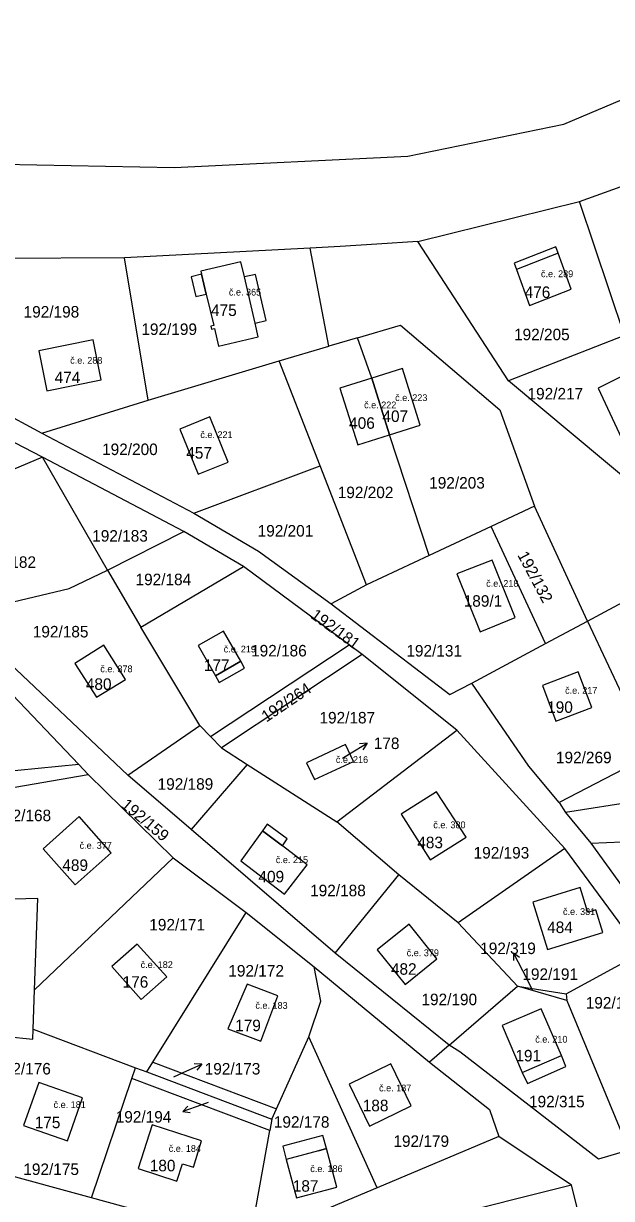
# Model space of a CAD drawing. Extents: x -887272 to -877616, y -1026687 to -1019819.
# Drawn here: x -882288.7 to -882201.9, y -1024193.7 to -1024020.3 of the extents above; entities that cross this region are included whole.
import ezdxf

# ---------------------------------------------------------------- set-up
doc = ezdxf.new("R2010")
doc.units = 0
for name, color, linetype in [('Definiční body', 7, 'Continuous'), ('Hranice parcel', 7, 'Continuous'), ('Parcelní čísla', 7, 'Continuous'), ('Polygon budovy', 7, 'Continuous'), ('Pop  PČ popisy', 7, 'Continuous'), ('Vnitřní kresba', 7, 'Continuous')]:
    doc.layers.add(name, color=color, linetype=linetype)

msp = doc.modelspace()

# ---------------------------------------------------------------- linework, layer by layer
at = {"layer": 'Hranice parcel'}
for p, q in [((-882206.58, -1024046.52), (-882188.26, -1024039.89)), ((-882230.46, -1024052.45), (-882206.58, -1024046.52)), ((-882199.93, -1024066.33), (-882206.58, -1024046.52)), ((-882217.07, -1024073.03), (-882230.46, -1024052.45)), ((-882246.33, -1024053.44), (-882273.78, -1024054.86)), ((-882243.61, -1024067.89), (-882246.33, -1024053.44)), ((-882273.78, -1024054.86), (-882294.43, -1024054.96)), ((-882270.28, -1024075.87), (-882273.78, -1024054.86)), ((-882199.93, -1024066.33), (-882217.07, -1024073.03)), ((-882250.94, -1024070.04), (-882243.61, -1024067.89)), ((-882239.34, -1024066.64), (-882243.61, -1024067.89)), ((-882237.27, -1024072.6), (-882239.34, -1024066.64)), ((-882270.28, -1024075.87), (-882250.94, -1024070.04)), ((-882244.88, -1024085.57), (-882250.94, -1024070.04)), ((-882237.27, -1024072.6), (-882234.62, -1024081)), ((-882196.2, -1024090.44), (-882217.07, -1024073.03)), ((-882294.27, -1024076.26), (-882285.96, -1024080.75)), ((-882285.96, -1024080.75), (-882270.28, -1024075.87)), ((-882285.87, -1024084.26), (-882291.31, -1024081.48)), ((-882285.96, -1024080.75), (-882263.54, -1024092.56)), ((-882228.8, -1024098.78), (-882234.62, -1024081)), ((-882285.87, -1024084.26), (-882304.9, -1024092.29)), ((-882276.26, -1024100.98), (-882285.87, -1024084.26)), ((-882265.03, -1024095.27), (-882285.87, -1024084.26)), ((-882263.54, -1024092.56), (-882244.88, -1024085.57)), ((-882238.02, -1024103.14), (-882244.88, -1024085.57)), ((-882213.21, -1024091.51), (-882219.65, -1024094.51)), ((-882205.42, -1024108.48), (-882213.21, -1024091.51)), ((-882276.26, -1024100.98), (-882265.03, -1024095.27)), ((-882256.19, -1024100.43), (-882265.03, -1024095.27)), ((-882219.65, -1024094.51), (-882228.8, -1024098.78)), ((-882211.61, -1024111.8), (-882219.65, -1024094.51)), ((-882228.8, -1024098.78), (-882238.02, -1024103.14)), ((-882276.26, -1024100.98), (-882271.37, -1024109.4)), ((-882271.37, -1024109.4), (-882256.19, -1024100.43)), ((-882240.6, -1024111.96), (-882256.19, -1024100.43)), ((-882238.02, -1024103.14), (-882243.24, -1024105.91)), ((-882205.42, -1024108.48), (-882198.92, -1024105.01)), ((-882273.27, -1024131.24), (-882298.33, -1024107.54)), ((-882262.64, -1024123.91), (-882271.37, -1024109.4)), ((-882211.61, -1024111.8), (-882205.42, -1024108.48)), ((-882261.07, -1024125.53), (-882240.6, -1024111.96)), ((-882238.67, -1024113.39), (-882240.6, -1024111.96)), ((-882222.5, -1024117.62), (-882211.61, -1024111.8)), ((-882238.67, -1024113.39), (-882259.45, -1024127.19)), ((-882224.7, -1024124.59), (-882238.67, -1024113.39)), ((-882273.27, -1024131.24), (-882262.64, -1024123.91)), ((-882262.64, -1024123.91), (-882261.07, -1024125.53)), ((-882242.43, -1024138.12), (-882224.7, -1024124.59)), ((-882224.7, -1024124.59), (-882208.75, -1024142.05)), ((-882259.45, -1024127.19), (-882261.07, -1024125.53)), ((-882259.45, -1024127.19), (-882255.64, -1024129.63)), ((-882280.53, -1024129.66), (-882306.6, -1024132.25)), ((-882280.53, -1024129.66), (-882279.12, -1024131.14)), ((-882255.64, -1024129.63), (-882263.95, -1024139.24)), ((-882255.64, -1024129.63), (-882242.43, -1024138.12)), ((-882295.03, -1024133.84), (-882279.12, -1024131.14)), ((-882279.12, -1024131.14), (-882266.59, -1024143.44)), ((-882263.95, -1024139.24), (-882273.27, -1024131.24)), ((-882190.49, -1024133.91), (-882208.64, -1024136.73)), ((-882209.58, -1024135.28), (-882208.64, -1024136.73)), ((-882208.64, -1024136.73), (-882204.92, -1024141.27)), ((-882242.67, -1024157.52), (-882263.95, -1024139.24)), ((-882233.24, -1024145.95), (-882242.43, -1024138.12)), ((-882204.92, -1024141.27), (-882175.35, -1024139.88)), ((-882208.75, -1024142.05), (-882224.52, -1024153.03)), ((-882197.43, -1024157.42), (-882208.75, -1024142.05)), ((-882204.92, -1024141.27), (-882191.8, -1024159.41)), ((-882266.59, -1024143.44), (-882287.05, -1024162.93)), ((-882266.59, -1024143.44), (-882255.81, -1024151.5)), ((-882242.67, -1024157.52), (-882233.24, -1024145.95)), ((-882224.52, -1024153.03), (-882233.24, -1024145.95)), ((-882286.58, -1024149.42), (-882291.94, -1024149.59)), ((-882287.05, -1024162.93), (-882286.58, -1024149.42)), ((-882269.58, -1024173.58), (-882255.81, -1024151.5)), ((-882255.81, -1024151.5), (-882245.77, -1024159.53)), ((-882231.74, -1024153.22), (-882236.46, -1024157.01)), ((-882215.75, -1024162.36), (-882224.52, -1024153.03)), ((-882225.84, -1024171.07), (-882242.67, -1024157.52)), ((-882208.53, -1024163.52), (-882197.43, -1024157.42)), ((-882245.77, -1024159.53), (-882228.75, -1024173.58)), ((-882287.25, -1024168.71), (-882287.05, -1024162.93)), ((-882225.84, -1024171.07), (-882215.75, -1024162.36)), ((-882215.75, -1024162.36), (-882208.53, -1024163.52)), ((-882208.46, -1024164.48), (-882215.75, -1024162.36)), ((-882208.53, -1024163.52), (-882208.46, -1024164.48)), ((-882208.46, -1024164.48), (-882199.3, -1024186.6)), ((-882287.25, -1024168.71), (-882272.13, -1024174.43)), ((-882251.31, -1024180.47), (-882246.53, -1024169.84)), ((-882236.46, -1024192.13), (-882246.53, -1024169.84)), ((-882225.84, -1024171.07), (-882228.75, -1024173.58)), ((-882270.49, -1024175.04), (-882269.58, -1024173.58)), ((-882269.58, -1024173.58), (-882251.31, -1024180.47)), ((-882272.67, -1024176.01), (-882272.13, -1024174.43)), ((-882272.13, -1024174.43), (-882270.49, -1024175.04)), ((-882270.49, -1024175.04), (-882252.01, -1024182.03)), ((-882278.63, -1024193.63), (-882272.67, -1024176.01)), ((-882252.31, -1024183.68), (-882272.67, -1024176.01)), ((-882252.01, -1024182.03), (-882251.31, -1024180.47)), ((-882252.01, -1024182.03), (-882252.31, -1024183.68)), ((-882255.25, -1024200.01), (-882252.31, -1024183.68)), ((-882218.48, -1024184.59), (-882236.46, -1024192.13)), ((-882207.74, -1024191.74), (-882218.48, -1024184.59)), ((-882278.63, -1024193.63), (-882294.85, -1024189.2)), ((-882236.46, -1024192.13), (-882255.25, -1024200.01)), ((-882207.74, -1024191.74), (-882227.58, -1024196.72)), ((-882204.37, -1024205.08), (-882207.74, -1024191.74)), ((-882255.25, -1024200.01), (-882278.63, -1024193.63))]:
    msp.add_line(p, q, dxfattribs=at)
for points in [[(-882340.1, -1024040.68), (-882291.8, -1024041.02), (-882266.44, -1024041.52), (-882231.92, -1024039.84), (-882208.92, -1024035.12), (-882179.22, -1024022.58), (-882174.49, -1024020.26)], [(-882230.46, -1024052.45), (-882236.52, -1024052.83), (-882241.91, -1024053.16), (-882246.33, -1024053.44)], [(-882209.75, -1024054.18), (-882210.09, -1024053.25), (-882216.22, -1024055.64), (-882215.88, -1024056.58), (-882213.96, -1024061.89), (-882207.81, -1024059.49), (-882209.75, -1024054.18)], [(-882254.49, -1024064.48), (-882252.87, -1024064.11), (-882254.44, -1024057.3), (-882256.06, -1024057.67), (-882256.57, -1024055.46), (-882262.49, -1024056.83), (-882262.38, -1024057.28), (-882263.95, -1024057.65), (-882263.24, -1024060.57), (-882261.69, -1024060.21), (-882260.59, -1024064.83), (-882261.03, -1024064.93), (-882260.91, -1024065.39), (-882260.48, -1024065.29)], [(-882260.48, -1024065.29), (-882259.87, -1024067.88), (-882254.02, -1024066.51), (-882254.49, -1024064.48)], [(-882239.34, -1024066.64), (-882233.03, -1024064.79), (-882218.36, -1024077.29), (-882213.21, -1024091.51)], [(-882186.22, -1024065.24), (-882203.83, -1024074.1), (-882196.2, -1024090.44)], [(-882277.2, -1024072.86), (-882278.42, -1024066.96), (-882286.44, -1024068.58), (-882285.22, -1024074.5), (-882277.2, -1024072.86)], [(-882234.62, -1024081), (-882230.09, -1024079.57), (-882230.63, -1024077.85), (-882232.74, -1024071.17), (-882237.27, -1024072.6)], [(-882237.27, -1024072.6), (-882241.95, -1024074.08), (-882239.3, -1024082.48), (-882234.62, -1024081)], [(-882262.9, -1024086.81), (-882258.46, -1024085), (-882261.17, -1024078.35), (-882265.61, -1024080.16), (-882262.9, -1024086.81)], [(-882263.54, -1024092.56), (-882253.97, -1024098.18), (-882243.24, -1024105.91)], [(-882298.33, -1024107.54), (-882281.94, -1024103.67), (-882276.26, -1024100.98)], [(-882224.69, -1024101.49), (-882221.25, -1024110.05), (-882216.06, -1024107.94), (-882219.46, -1024099.5), (-882224.69, -1024101.49)], [(-882243.24, -1024105.91), (-882225.71, -1024119.34), (-882222.5, -1024117.62)], [(-882303.23, -1024108.62), (-882291.29, -1024118.32), (-882280.53, -1024129.66)], [(-882205.42, -1024108.48), (-882196.11, -1024128.27), (-882209.58, -1024135.28)], [(-882259.17, -1024109.96), (-882262.9, -1024112.1), (-882260.34, -1024116.56), (-882259.77, -1024117.56), (-882256.04, -1024115.42), (-882256.61, -1024114.42), (-882259.17, -1024109.96)], [(-882276.8, -1024112.01), (-882281.11, -1024114.74), (-882277.9, -1024119.72)], [(-882277.9, -1024119.72), (-882273.64, -1024117.11), (-882276.8, -1024112.01)], [(-882206.79, -1024115.98), (-882212.07, -1024117.99), (-882210.06, -1024123.27), (-882204.78, -1024121.26), (-882206.79, -1024115.98)], [(-882209.58, -1024135.28), (-882214.07, -1024129.89), (-882222.5, -1024117.62)], [(-882239.95, -1024129.23), (-882241.14, -1024126.7), (-882246.89, -1024129.39), (-882245.73, -1024131.88), (-882239.95, -1024129.23)], [(-882232.9, -1024136.97), (-882228.63, -1024143.71), (-882223.31, -1024140.39), (-882227.68, -1024133.67), (-882232.9, -1024136.97)], [(-882280.47, -1024137.35), (-882285.76, -1024142.1), (-882281.04, -1024147.43), (-882275.73, -1024142.69), (-882280.47, -1024137.35)], [(-882250.44, -1024141.66), (-882249.76, -1024140.6), (-882252.7, -1024138.44), (-882253.4, -1024139.42), (-882256.6, -1024143.89), (-882250.16, -1024148.8), (-882246.78, -1024144.44), (-882250.44, -1024141.66)], [(-882204.16, -1024151.1), (-882205.35, -1024151.48), (-882206.5, -1024147.81), (-882213.47, -1024149.97), (-882211.29, -1024156.96), (-882203.13, -1024154.43), (-882204.16, -1024151.1)], [(-882236.46, -1024157.01), (-882232.35, -1024162.12), (-882227.63, -1024158.33), (-882231.74, -1024153.22)], [(-882271.32, -1024164.34), (-882267.54, -1024160.98), (-882271.88, -1024156.18), (-882275.64, -1024159.48), (-882271.32, -1024164.34)], [(-882246.53, -1024169.84), (-882244.78, -1024164.57), (-882245.77, -1024159.53)], [(-882253.64, -1024170.5), (-882251.12, -1024163.82), (-882255.66, -1024162.1), (-882258.5, -1024168.66), (-882253.64, -1024170.5)], [(-882215.03, -1024175.11), (-882214.26, -1024176.72), (-882208.6, -1024174.25), (-882209.22, -1024172.63), (-882212.26, -1024165.7), (-882218.01, -1024168.17), (-882215.03, -1024175.11)], [(-882295.13, -1024169.42), (-882287.3, -1024170.21), (-882287.25, -1024168.71)], [(-882199.3, -1024186.6), (-882203.76, -1024187.9), (-882224.27, -1024172.09), (-882225.84, -1024171.07)], [(-882237.58, -1024183.02), (-882231.43, -1024180.03), (-882234.46, -1024173.84), (-882240.59, -1024176.84), (-882237.58, -1024183.02)], [(-882228.75, -1024173.58), (-882219.88, -1024180.56), (-882218.48, -1024184.59)], [(-882279.97, -1024178.86), (-882286.44, -1024176.59), (-882288.66, -1024182.92), (-882282.18, -1024185.19), (-882279.97, -1024178.86)], [(-882263.59, -1024189.1), (-882262.38, -1024185.19), (-882269.68, -1024182.83), (-882271.77, -1024189.3), (-882266.04, -1024191.15), (-882265.21, -1024188.58), (-882263.59, -1024189.1)], [(-882244.46, -1024184.4), (-882250.4, -1024185.99), (-882249.88, -1024187.94), (-882248.36, -1024193.62), (-882242.42, -1024192.03), (-882243.94, -1024186.35), (-882244.46, -1024184.4)]]:
    msp.add_lwpolyline(points, dxfattribs=at)
at = {"layer": 'Polygon budovy'}
for points in [[(-882207.81, -1024059.49), (-882209.75, -1024054.18), (-882215.88, -1024056.58), (-882213.96, -1024061.89)], [(-882254.49, -1024064.48), (-882256.06, -1024057.67), (-882256.57, -1024055.46), (-882262.49, -1024056.83), (-882262.38, -1024057.28), (-882261.69, -1024060.21), (-882260.59, -1024064.83), (-882261.03, -1024064.93), (-882260.91, -1024065.39), (-882260.48, -1024065.29), (-882259.87, -1024067.88), (-882254.02, -1024066.51)], [(-882286.44, -1024068.58), (-882285.22, -1024074.5), (-882277.2, -1024072.86), (-882278.42, -1024066.96)], [(-882234.62, -1024081), (-882230.09, -1024079.57), (-882230.63, -1024077.85), (-882232.74, -1024071.17), (-882237.27, -1024072.6)], [(-882234.62, -1024081), (-882237.27, -1024072.6), (-882241.95, -1024074.08), (-882239.3, -1024082.48)], [(-882261.17, -1024078.35), (-882265.61, -1024080.16), (-882262.9, -1024086.81), (-882258.46, -1024085)], [(-882216.06, -1024107.94), (-882219.46, -1024099.5), (-882224.69, -1024101.49), (-882221.25, -1024110.05)], [(-882256.61, -1024114.42), (-882259.17, -1024109.96), (-882262.9, -1024112.1), (-882260.34, -1024116.56)], [(-882276.8, -1024112.01), (-882281.11, -1024114.74), (-882277.9, -1024119.72), (-882273.64, -1024117.11)], [(-882204.78, -1024121.26), (-882206.79, -1024115.98), (-882212.07, -1024117.99), (-882210.06, -1024123.27)], [(-882241.14, -1024126.7), (-882246.89, -1024129.39), (-882245.73, -1024131.88), (-882239.95, -1024129.23)], [(-882232.9, -1024136.97), (-882228.63, -1024143.71), (-882223.31, -1024140.39), (-882227.68, -1024133.67)], [(-882285.76, -1024142.1), (-882281.04, -1024147.43), (-882275.73, -1024142.69), (-882280.47, -1024137.35)], [(-882250.44, -1024141.66), (-882253.4, -1024139.42), (-882256.6, -1024143.89), (-882250.16, -1024148.8), (-882246.78, -1024144.44)], [(-882203.13, -1024154.43), (-882204.16, -1024151.1), (-882205.35, -1024151.48), (-882206.5, -1024147.81), (-882213.47, -1024149.97), (-882211.29, -1024156.96)], [(-882231.74, -1024153.22), (-882236.46, -1024157.01), (-882232.35, -1024162.12), (-882227.63, -1024158.33)], [(-882271.32, -1024164.34), (-882267.54, -1024160.98), (-882271.88, -1024156.18), (-882275.64, -1024159.48)], [(-882258.5, -1024168.66), (-882253.64, -1024170.5), (-882251.12, -1024163.82), (-882255.66, -1024162.1)], [(-882218.01, -1024168.17), (-882215.03, -1024175.11), (-882209.22, -1024172.63), (-882212.26, -1024165.7)], [(-882240.59, -1024176.84), (-882237.58, -1024183.02), (-882231.43, -1024180.03), (-882234.46, -1024173.84)], [(-882286.44, -1024176.59), (-882288.66, -1024182.92), (-882282.18, -1024185.19), (-882279.97, -1024178.86)], [(-882266.04, -1024191.15), (-882265.21, -1024188.58), (-882263.59, -1024189.1), (-882262.38, -1024185.19), (-882269.68, -1024182.83), (-882271.77, -1024189.3)], [(-882243.94, -1024186.35), (-882245.1, -1024186.66), (-882249.88, -1024187.94), (-882248.36, -1024193.62), (-882242.42, -1024192.03)]]:
    msp.add_lwpolyline(points, close=True, dxfattribs=at)
at = {"layer": 'Pop  PČ popisy'}
for p, q in [((-882240.53, -1024128.07), (-882237.96, -1024126.52)), ((-882237.96, -1024126.52), (-882239.07, -1024126.61)), ((-882237.96, -1024126.52), (-882238.56, -1024127.47)), ((-882241.58, -1024128.7), (-882240.53, -1024128.07)), ((-882214.97, -1024160.12), (-882216.33, -1024157.45)), ((-882216.33, -1024157.45), (-882215.43, -1024158.11)), ((-882216.33, -1024157.45), (-882216.32, -1024158.57)), ((-882213.53, -1024162.91), (-882214.97, -1024160.12)), ((-882265.1, -1024175.13), (-882262.36, -1024173.91)), ((-882262.36, -1024173.91), (-882263.48, -1024173.86)), ((-882262.36, -1024173.91), (-882263.07, -1024174.77)), ((-882266.48, -1024175.76), (-882265.1, -1024175.13)), ((-882262.36, -1024179.87), (-882265.18, -1024180.9)), ((-882265.18, -1024180.9), (-882264.41, -1024180.08)), ((-882265.18, -1024180.9), (-882264.07, -1024181.02)), ((-882261.43, -1024179.53), (-882262.36, -1024179.87))]:
    msp.add_line(p, q, dxfattribs=at)
at = {"layer": 'Vnitřní kresba'}
for p, q in [((-882209.75, -1024054.18), (-882215.88, -1024056.58)), ((-882261.69, -1024060.21), (-882262.38, -1024057.28)), ((-882254.49, -1024064.48), (-882256.06, -1024057.67)), ((-882256.61, -1024114.42), (-882260.34, -1024116.56)), ((-882253.4, -1024139.42), (-882250.44, -1024141.66)), ((-882215.03, -1024175.11), (-882209.22, -1024172.63)), ((-882245.1, -1024186.66), (-882249.88, -1024187.94)), ((-882245.1, -1024186.66), (-882243.94, -1024186.35))]:
    msp.add_line(p, q, dxfattribs=at)

# ---------------------------------------------------------------- texts
at = {"layer": 'Definiční body'}
for s, p in [('č.e. 289', (-882212.27, -1024057.71)), ('č.e. 365', (-882258.35, -1024060.42)), ('č.e. 288', (-882281.79, -1024070.49)), ('č.e. 223', (-882233.8, -1024076)), ('č.e. 222', (-882238.39, -1024077.07)), ('č.e. 221', (-882262.57, -1024081.46)), ('č.e. 218', (-882220.36, -1024103.42)), ('č.e. 219', (-882259.12, -1024113.11)), ('č.e. 378', (-882277.34, -1024116.03)), ('č.e. 217', (-882208.71, -1024119.21)), ('č.e. 216', (-882242.56, -1024129.42)), ('č.e. 380', (-882228.17, -1024139.06)), ('č.e. 377', (-882280.4, -1024142.1)), ('č.e. 215', (-882251.42, -1024144.21)), ('č.e. 381', (-882209.02, -1024151.86)), ('č.e. 379', (-882232.1, -1024157.95)), ('č.e. 182', (-882271.39, -1024159.7)), ('č.e. 183', (-882254.44, -1024165.72)), ('č.e. 210', (-882213.12, -1024170.71)), ('č.e. 187', (-882236.18, -1024177.91)), ('č.e. 181', (-882284.24, -1024180.36)), ('č.e. 184', (-882267.24, -1024186.84)), ('č.e. 186', (-882246.33, -1024189.82))]:
    msp.add_text(s, height=1, dxfattribs=at).set_placement(p)
at = {"layer": 'Parcelní čísla'}
for s, p in [('476', (-882214.69, -1024060.78)), ('192/198', (-882288.67, -1024063.67)), ('475', (-882260.99, -1024063.44)), ('192/199', (-882271.28, -1024066.24)), ('192/205', (-882216.25, -1024067.02)), ('474', (-882284.08, -1024073.35)), ('192/217', (-882214.26, -1024075.76)), ('406', (-882240.6, -1024080.09)), ('407', (-882235.68, -1024079.08)), ('192/200', (-882277.08, -1024083.97)), ('457', (-882264.65, -1024084.49)), ('192/203', (-882228.78, -1024088.92)), ('192/202', (-882242.28, -1024090.33)), ('192/201', (-882254.11, -1024096)), ('192/183', (-882278.54, -1024096.75)), ('192/182', (-882295.05, -1024100.62)), ('192/184', (-882272.14, -1024103.18)), ('189/1', (-882223.68, -1024106.36)), ('192/185', (-882287.31, -1024110.89)), ('192/186', (-882255.08, -1024113.7)), ('192/131', (-882232.15, -1024113.71)), ('177', (-882262.05, -1024115.84)), ('480', (-882279.48, -1024118.63)), ('192/187', (-882244.98, -1024123.59)), ('190', (-882211.36, -1024122.03)), ('178', (-882236.96, -1024127.37)), ('192/269', (-882210.06, -1024129.46)), ('192/189', (-882268.88, -1024133.38)), ('192/168', (-882292.82, -1024138.02)), ('483', (-882230.54, -1024142.01)), ('192/193', (-882222.22, -1024143.53)), ('489', (-882282.95, -1024145.36)), ('409', (-882253.99, -1024147.05)), ('192/188', (-882246.36, -1024149.1)), ('192/171', (-882270.11, -1024154.15)), ('484', (-882211.36, -1024154.53)), ('192/319', (-882221.25, -1024157.64)), ('192/172', (-882258.44, -1024160.95)), ('482', (-882234.43, -1024160.69)), ('192/191', (-882215.02, -1024161.45)), ('176', (-882274.05, -1024162.6)), ('192/190', (-882229.92, -1024165.18)), ('192/192', (-882205.66, -1024165.68)), ('179', (-882257.43, -1024169.02)), ('191', (-882216.05, -1024173.48)), ('192/176', (-882292.86, -1024175.41)), ('192/173', (-882261.93, -1024175.42)), ('188', (-882238.59, -1024180.84)), ('192/315', (-882214.04, -1024180.26)), ('192/194', (-882275.07, -1024182.51)), ('175', (-882287.03, -1024183.34)), ('192/178', (-882251.72, -1024183.27)), ('192/179', (-882234.06, -1024186.1)), ('192/175', (-882288.71, -1024190.25)), ('180', (-882270.04, -1024189.71)), ('187', (-882248.92, -1024192.72))]:
    msp.add_text(s, height=1.7, dxfattribs=at).set_placement(p)
for s, rotation, p in [('192/132', 298, (-882215.8, -1024098.72)), ('192/181', 324, (-882246.42, -1024107.91)), ('192/264', 34, (-882252.82, -1024123.47)), ('192/159', 320, (-882274.39, -1024135.84))]:
    msp.add_text(s, height=1.7, rotation=rotation, dxfattribs=at).set_placement(p)

doc.saveas('drawing.dxf')
